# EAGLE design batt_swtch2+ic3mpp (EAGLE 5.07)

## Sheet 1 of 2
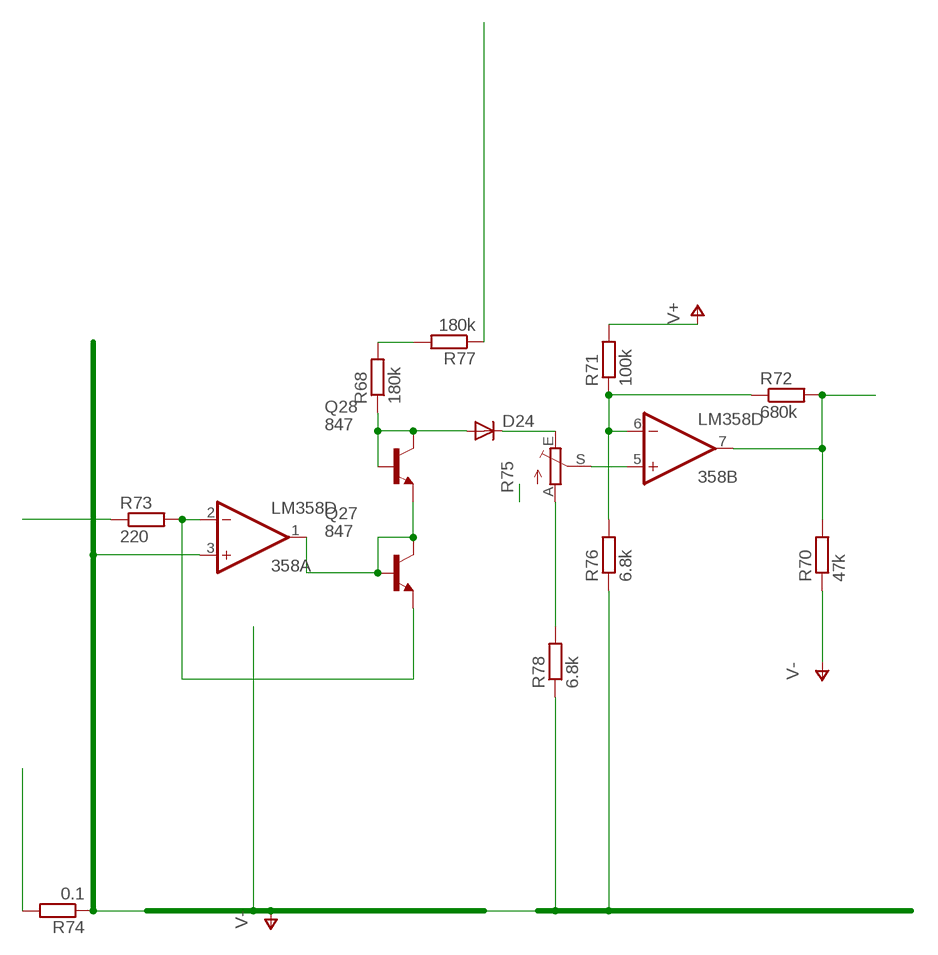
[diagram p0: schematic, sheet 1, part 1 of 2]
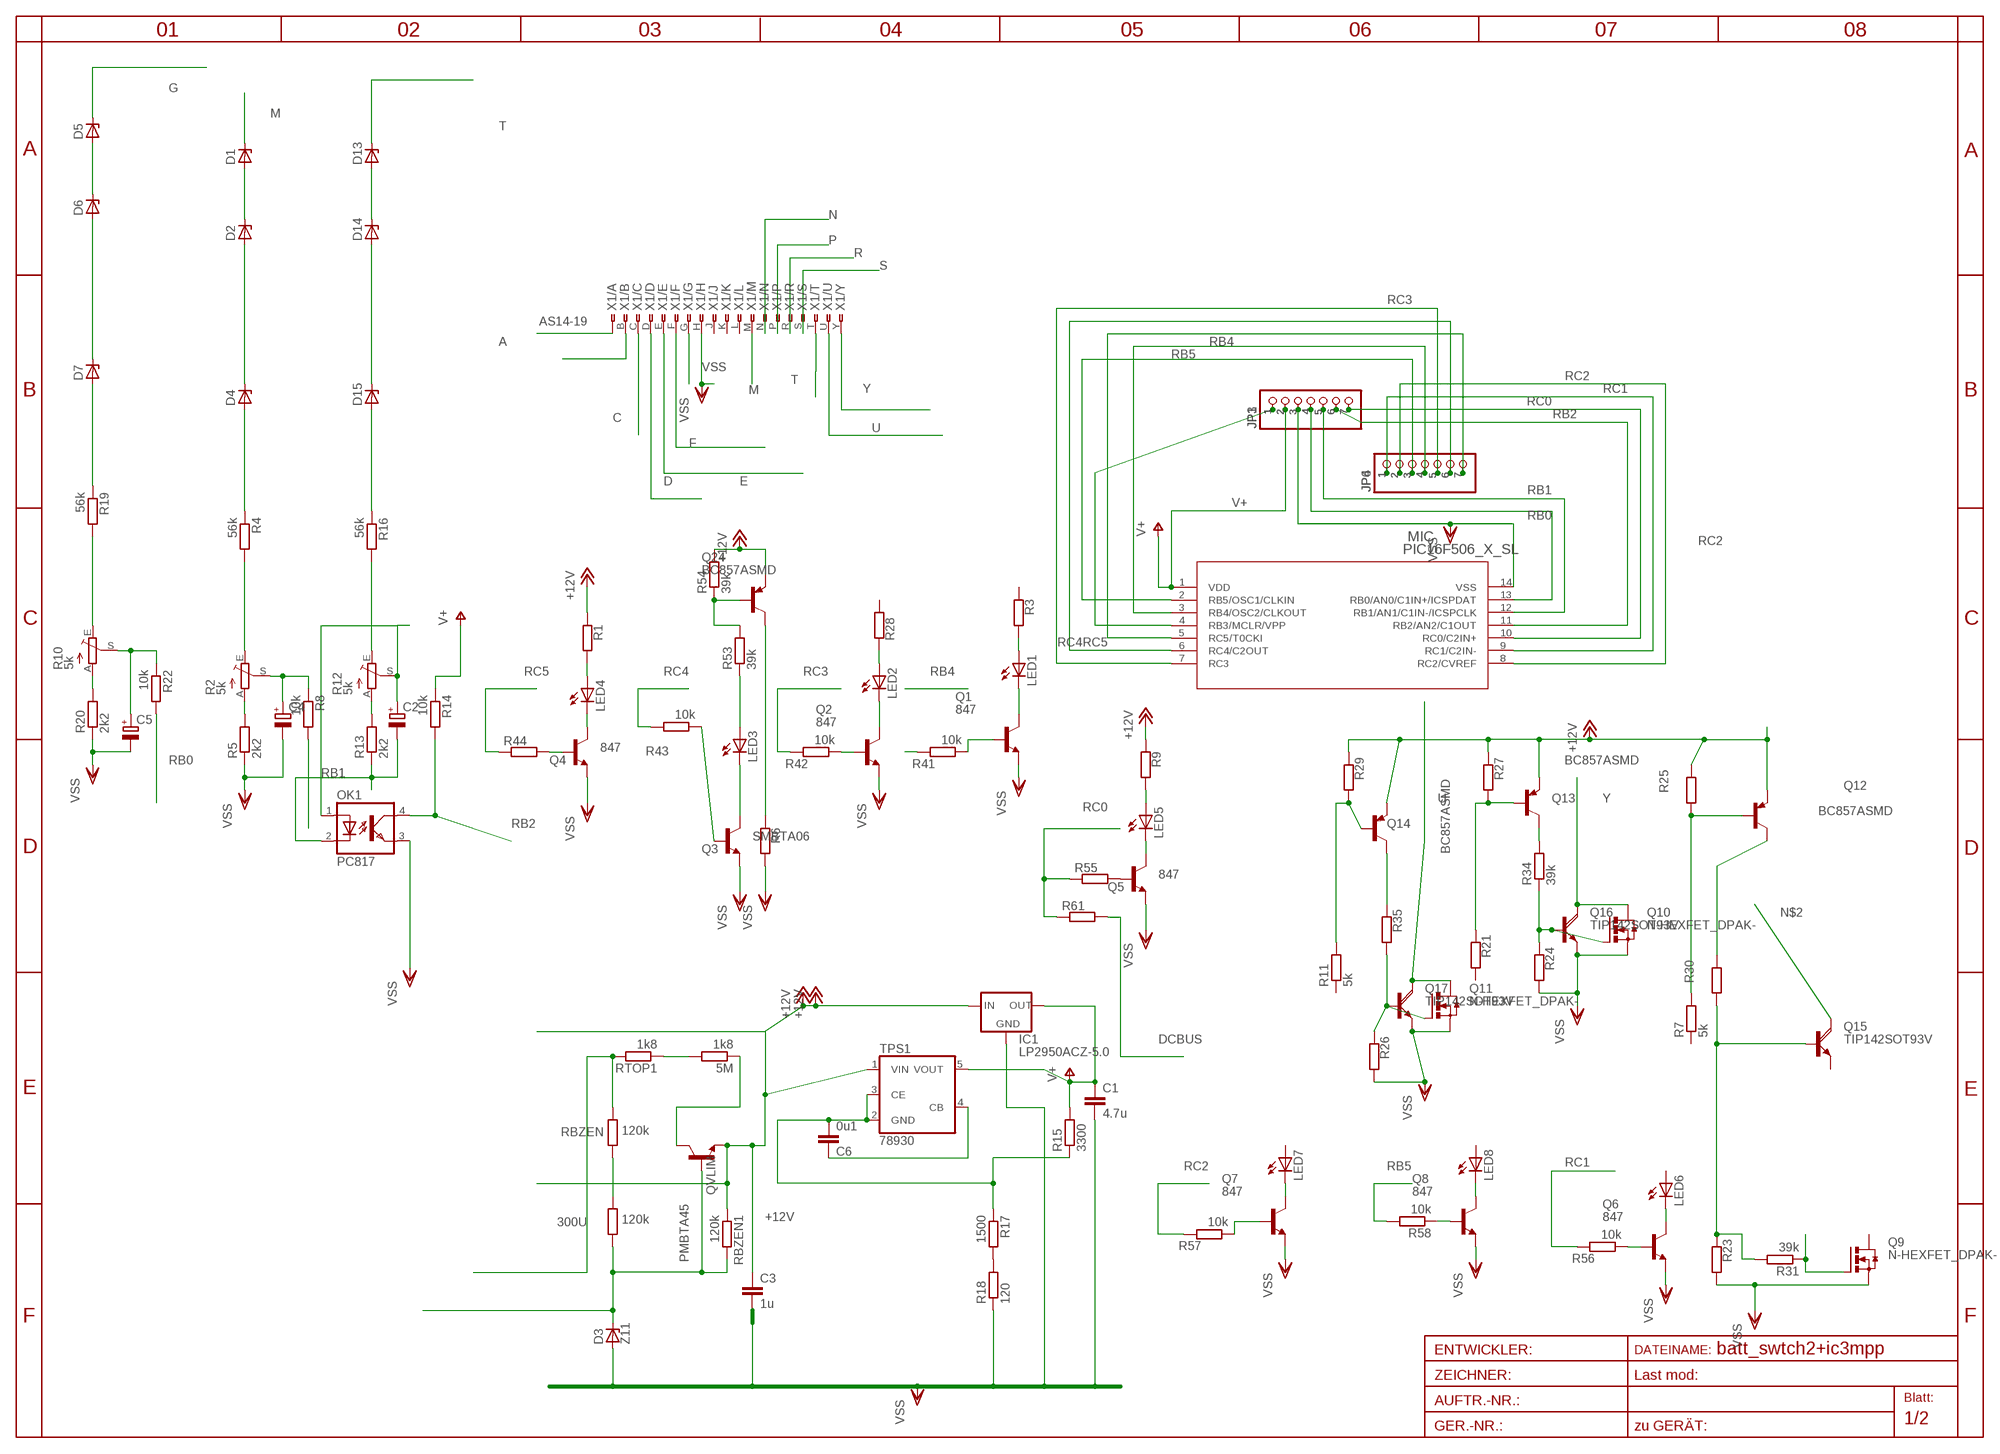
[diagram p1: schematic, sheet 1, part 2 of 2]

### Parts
5M  1k8  R-EU_R1206  [R1206]
300U  120k  R-EU_R1206  [R1206]
358  LM358D  [SO08]
C1  4.7u  C-EUC1206  [C1206]
C2  CPOL-EUE2,5-6E  [E2,5-6E]
C3  1u  C-EUC1206  [C1206]
C4  CPOL-EUE2,5-6E  [E2,5-6E]
C5  CPOL-EUE2,5-6E  [E2,5-6E]
C6  0u1  C-EUC0805  [C0805]
D1  ZENER-DIODESOD80C  [SOD80C]
D2  ZENER-DIODESOD80C  [SOD80C]
D3  Z11  ZENER-DIODESOD80C  [SOD80C]
D4  ZENER-DIODESOD80C  [SOD80C]
D5  ZENER-DIODESOD80C  [SOD80C]
D6  ZENER-DIODESOD80C  [SOD80C]
D7  ZENER-DIODESOD80C  [SOD80C]
D13  ZENER-DIODESOD80C  [SOD80C]
D14  ZENER-DIODESOD80C  [SOD80C]
D15  ZENER-DIODESOD80C  [SOD80C]
D24  DIODE-SOD80C  [SOD80C]
IC1  LP2950ACZ-5.0  [TO92]
JP1  PINHD-1X7  [1X07]
JP3  PINHD-1X7  [1X07]
JP4  PINHD-1X7  [1X07]
JP6  PINHD-1X7  [1X07]
LED1  LEDCHIPLED_1206  [CHIPLED_1206]
LED2  LEDCHIPLED_1206  [CHIPLED_1206]
LED3  LEDCHIPLED_1206  [CHIPLED_1206]
LED4  LEDCHIPLED_1206  [CHIPLED_1206]
LED5  LEDCHIPLED_1206  [CHIPLED_1206]
LED6  LEDCHIPLED_1206  [CHIPLED_1206]
LED7  LEDCHIPLED_1206  [CHIPLED_1206]
LED8  LEDCHIPLED_1206  [CHIPLED_1206]
MIC  PIC16F506_X_SL  [SOIC14_N_MC]
OK1  PC817  [DIL04]
Q1  847  BC847ASMD  [SOT23]
Q2  847  BC847ASMD  [SOT23]
Q3  SMBTA06  BC847ASMD  [SOT23]
Q4  847  BC847ASMD  [SOT23]
Q5  847  BC847ASMD  [SOT23]
Q6  847  BC847ASMD  [SOT23]
Q7  847  BC847ASMD  [SOT23]
Q8  847  BC847ASMD  [SOT23]
Q9  N-HEXFET_DPAK-  [TO252]
Q10  N-HEXFET_DPAK-  [TO252]
Q11  N-HEXFET_DPAK-  [TO252]
Q12  BC857ASMD  [SOT23-BEC]
Q13  BC857ASMD  [SOT23-BEC]
Q14  BC857ASMD  [SOT23-BEC]
Q15  TIP142SOT93V  [SOT93V]
Q16  TIP142SOT93V  [SOT93V]
Q17  TIP142SOT93V  [SOT93V]
Q24  BC857ASMD  [SOT23-BEC]
Q27  847  BC847ALT1SMD  [SOT23]
Q28  847  BC847ALT1SMD  [SOT23]
QVLIM  PMBTA45  BC847ALT1SMD  [SOT23]
R1  39k  R-EU_R0805  [R0805]
R2  5k  TRIM_EU-S64W  [S64W]
R3  39k  R-EU_R0805  [R0805]
R4  56k  R-EU_R0805  [R0805]
R5  2k2  R-EU_R0805  [R0805]
R6  39k  R-EU_R0805  [R0805]
R7  5k  R-EU_R0805  [R0805]
R8  10k  R-EU_R0805  [R0805]
R9  5k  R-EU_R0805  [R0805]
R10  5k  TRIM_EU-S64W  [S64W]
R11  5k  R-EU_R0805  [R0805]
R12  5k  TRIM_EU-S64W  [S64W]
R13  2k2  R-EU_R0805  [R0805]
R14  10k  R-EU_R0805  [R0805]
R15  3300  R-EU_R0805  [R0805]
R16  56k  R-EU_R0805  [R0805]
R17  1500  R-EU_R0805  [R0805]
R18  120  R-EU_R0805  [R0805]
R19  56k  R-EU_R0805  [R0805]
R20  2k2  R-EU_R0805  [R0805]
R21  5k  R-EU_R0805  [R0805]
R22  10k  R-EU_R0805  [R0805]
R23  39k  R-EU_R0805  [R0805]
R24  39k  R-EU_R0805  [R0805]
R25  39k  R-EU_R0805  [R0805]
R26  39k  R-EU_R0805  [R0805]
R27  39k  R-EU_R0805  [R0805]
R28  39k  R-EU_R0805  [R0805]
R29  39k  R-EU_R0805  [R0805]
R30  39k  R-EU_R0805  [R0805]
R31  39k  R-EU_R0805  [R0805]
R34  39k  R-EU_R0805  [R0805]
R35  39k  R-EU_R0805  [R0805]
R41  10k  R-EU_R0805  [R0805]
R42  10k  R-EU_R0805  [R0805]
R43  10k  R-EU_R0805  [R0805]
R44  10k  R-EU_R0805  [R0805]
R53  39k  R-EU_R0805  [R0805]
R54  39k  R-EU_R0805  [R0805]
R55  10k  R-EU_R0805  [R0805]
R56  10k  R-EU_R0805  [R0805]
R57  10k  R-EU_R0805  [R0805]
R58  10k  R-EU_R0805  [R0805]
R61  10k  R-EU_R0805  [R0805]
R68  180k  R-EU_R1206  [R1206]
R70  47k  R-EU_R0805  [R0805]
R71  100k  R-EU_R0805  [R0805]
R72  680k  R-EU_R1206  [R1206]
R73  220  R-EU_R0805  [R0805]
R74  0.1  R-EU_R2512  [R2512]
R75  TRIM_EU-S64W  [S64W]
R76  6.8k  R-EU_R0805  [R0805]
R77  180k  R-EU_R1206  [R1206]
R78  6.8k  R-EU_R0805  [R0805]
RBZEN  120k  R-EU_R1206  [R1206]
RBZEN1  120k  R-EU_R0805  [R0805]
RTOP1  1k8  R-EU_R1206  [R1206]
TPS1  78930  TPS78930SOT23-5  [SOT25]
X1  AS14-19  AS14-19OLIVE  [Y28M-19TK]

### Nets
+12V: C3.1 IC1.3(IN) Q12.E Q13.E Q14.E Q24.E QVLIM.2(E) R1.2 R9.2 R25.2 R27.2 R29.2 R54.2 RBZEN1.1 TPS1.1(VIN) ; also sheet 2
A: X1.A ; also sheet 2
BOOST_EN: Q24.C R6.2 ; also sheet 2
C: X1.C
CB: 300U.2 D3.C QVLIM.1(B) RBZEN1.2 ; also sheet 2
D: X1.D
DCBUS: R61.1 ; also sheet 2
E: X1.E
F: X1.F
G: D5.C RBZEN.1 RTOP1.2 X1.G ; also sheet 2
GND1: C6.1 TPS1.4(CB)
M: D1.C X1.M
N: X1.N
N$1: 300U.1 RBZEN.2
N$2: Q15.C
N$4: Q8.1(B) R58.1
N$5: C2.+ OK1.1(A) R12.S
N$6: Q3.1(B) R43.1
N$7: LED6.C Q6.3(C)
N$8: R17.2 R18.2
N$9: R41.2
N$10: LED8.C Q8.3(C)
N$11: Q2.1(B) R42.1
N$12: Q1.1(B) R41.1
N$14: Q5.1(B) R55.1
N$16: 5M.1 QVLIM.3(C)
N$17: LED7.C Q7.3(C)
N$18: D15.A R16.1
N$19: LED1.C Q1.3(C)
N$20: LED1.A R3.1
N$21: Q14.B R11.2 R29.1
N$22: LED2.C Q2.3(C)
N$23: D14.A D15.C
N$24: D13.A D14.C
N$25: LED2.A R28.1
N$26: R12.A R13.2
N$28: Q6.1(B) R56.1
N$29: 5M.2 RTOP1.1
N$30: Q4.1(B) R44.1
N$31: Q7.1(B) R57.1
N$32: LED3.C Q3.3(C)
N$33: LED4.C Q4.3(C)
N$34: D7.A R19.1
N$35: D6.A D7.C
N$36: LED4.A R1.1
N$37: Q12.C R30.2
N$38: D5.A D6.C
N$39: R10.E R19.2
N$40: R10.A R20.2
N$41: D4.A R4.1
N$42: D2.A D4.C
N$43: D1.A D2.C
N$44: R2.E R4.2
N$45: R2.A R5.2
N$46: C4.+ R2.S R8.1
N$47: LED5.A R9.1
N$48: C5.+ R10.S R22.1
N$49: Q14.C R35.2
N$50: Q15.B R23.2 R30.1 R31.2
N$51: Q10.1(G) Q16.B R24.2 R34.1
N$52: LED5.C Q5.3(C)
N$53: Q12.B R7.2 R25.1
N$54: Q9.1(G) R31.1
N$55: Q13.B R21.2 R27.1
N$57: Q13.C R34.2
N$59: Q11.1(G) Q17.B R26.2 R35.1
N$65: R12.E R16.2
N$75: 358.2(A:-IN) Q27.2(E) R73.2
N$81: Q24.B R53.2 R54.1
N$82: LED3.A R53.1
N$85: 358.1(A:OUT) Q27.1(B) Q27.3(C) Q28.2(E)
N$88: D24.A Q28.1(B) Q28.3(C) R68.1
N$90: R73.1 R74.2
N$91: D24.C R75.E
N$92: 358.5(B:+IN) R75.S
N$93: 358.6(B:-IN) R71.1 R72.1 R76.2
N$94: R68.2 R77.2
N$95: 358.7(B:OUT) R70.2 R72.2
N$97: R75.A R78.2
P: X1.P
R: X1.R
RB0: JP1.4 JP3.4 MIC.13(RB0/AN0/C1IN+/ICSPDAT) R22.2
RB1: JP1.5 JP3.5 MIC.12(RB1/AN1/C1IN-/ICSPCLK) R8.2
RB2: JP1.6 JP3.6 MIC.11(RB2/AN2/C1OUT) OK1.4(COL) R14.2
RB4: JP4.4 JP6.4 MIC.3(RB4/OSC2/CLKOUT)
RB5: JP4.3 JP6.3 MIC.2(RB5/OSC1/CLKIN) R58.2
RC0: JP1.7 JP3.7 MIC.10(RC0/C2IN+) R55.2 R61.2
RC1: JP4.1 JP6.1 MIC.9(RC1/C2IN-) R56.2
RC2: JP4.2 JP6.2 MIC.8(RC2/CVREF) R57.2
RC3: JP4.5 JP6.5 MIC.7(RC3) R42.2
RC4: JP4.6 JP6.6 MIC.6(RC4/C2OUT) R43.2
RC5: JP4.7 JP6.7 MIC.5(RC5/T0CKI) R44.2
S: C2.- OK1.2(C) R13.1 X1.S
T: D13.C X1.T
U: Q11.3(D) Q17.C X1.U
V+: C1.1 IC1.1(OUT) JP1.2 JP3.2 MIC.1(VDD) R14.1 R15.2 R71.2 TPS1.5(VOUT)
V-: 358.3(A:+IN) C6.2 R15.1 R17.1 R70.1 R74.1 R76.1 R78.1 TPS1.2(GND) TPS1.3(CE)
VPLUS: R77.1
VSS: C1.2 C3.2 C4.- C5.- D3.A IC1.2(GND) JP1.3 JP3.3 MIC.14(VSS) OK1.3(EMIT) Q1.2(E) Q2.2(E) Q3.2(E) Q4.2(E) Q5.2(E) Q6.2(E) Q7.2(E) Q8.2(E) Q9.2(S) Q10.2(S) Q11.2(S) Q16.E Q17.E R5.1 R6.1 R18.1 R20.1 R23.1 R24.1 R26.1 X1.B X1.H ; also sheet 2
WIND: JP1.1 JP3.1 MIC.4(RB3/MCLR/VPP)
Y: Q10.3(D) Q16.C X1.Y
Unconnected: LED6.A LED7.A LED8.A Q9.3(D) Q15.E R3.2 R7.1 R11.1 R21.1 R28.2 X1.J X1.K X1.L

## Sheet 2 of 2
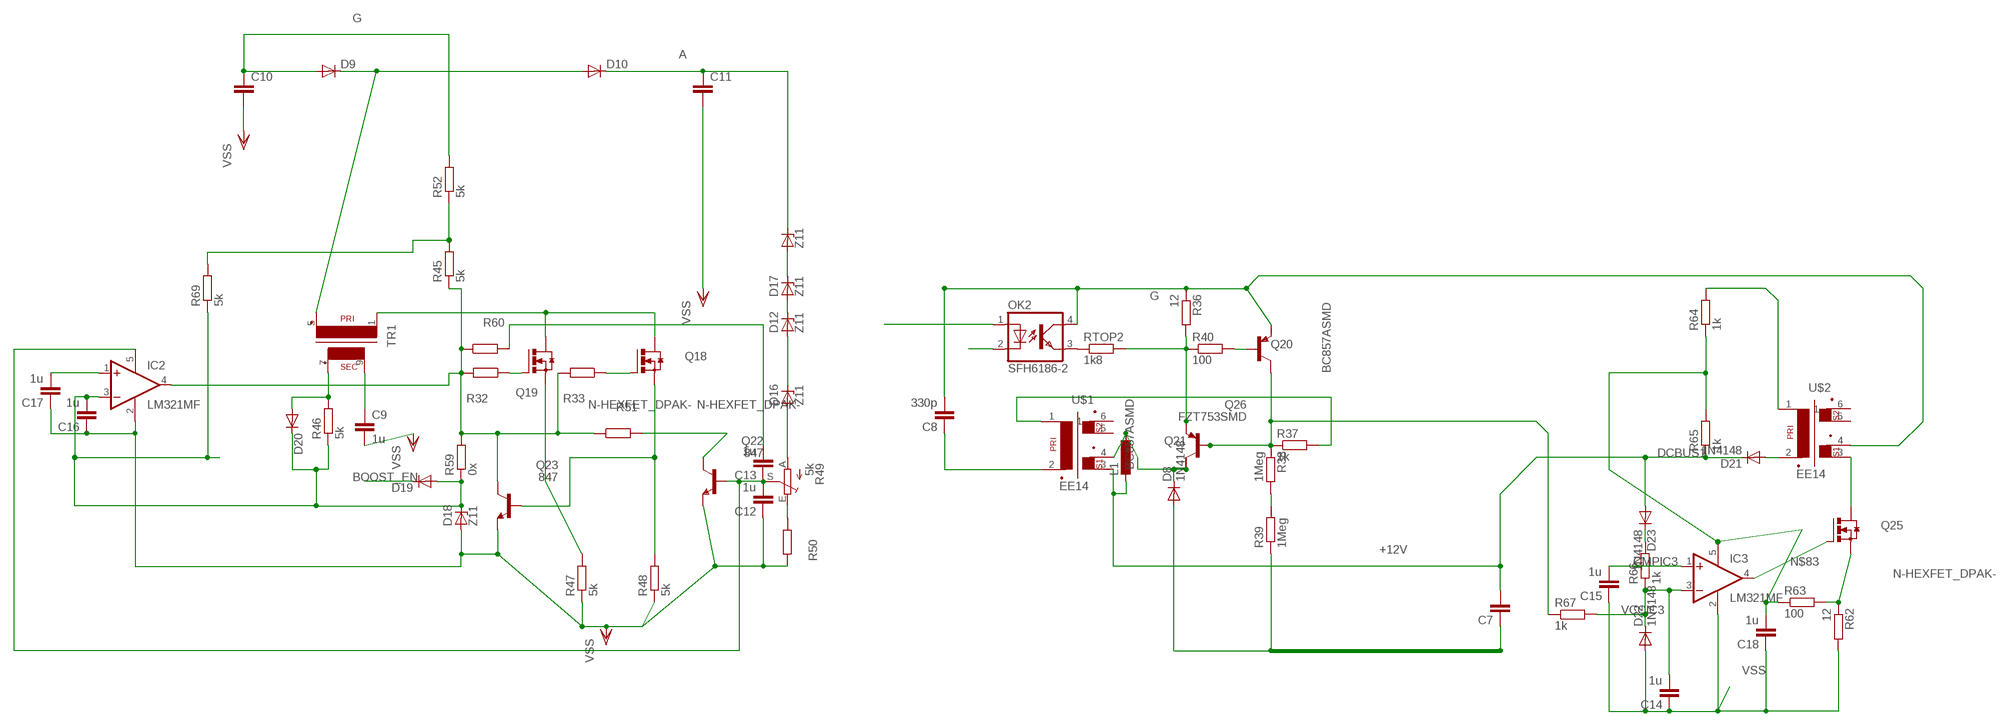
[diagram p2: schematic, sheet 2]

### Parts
C7  C-EU025-025X050  [C025-025X050]
C8  330p  C-EUC0805  [C0805]
C9  1u  C-EUC1206  [C1206]
C10  C-EU075-052X106  [C075-052X106]
C11  C-EU075-052X106  [C075-052X106]
C12  1u  C-EUC1206  [C1206]
C13  1u  C-EUC1206  [C1206]
C14  1u  C-EUC0805  [C0805]
C15  1u  C-EUC0805  [C0805]
C16  1u  C-EUC0805  [C0805]
C17  1u  C-EUC0805  [C0805]
C18  1u  C-EUC0805  [C0805]
D8  1N4148  DIODE-SMA-DO214  [SMA-DO214AC]
D9  DIODE-SMC  [SMC]
D10  DIODE-SMC  [SMC]
D11  Z11  ZENER-DIODESOD80C  [SOD80C]
D12  Z11  ZENER-DIODESOD80C  [SOD80C]
D16  Z11  ZENER-DIODESOD80C  [SOD80C]
D17  Z11  ZENER-DIODESOD80C  [SOD80C]
D18  Z11  ZENER-DIODESOD80C  [SOD80C]
D19  DIODE-MINIMELF  [MINIMELF]
D20  DIODE-MINIMELF  [MINIMELF]
D21  1N4148  DIODE-SMA-DO214  [SMA-DO214AC]
D22  1N4148  DIODE-SMA-DO214  [SMA-DO214AC]
D23  1N4148  DIODE-SMA-DO214  [SMA-DO214AC]
IC2  LM321MF  [SOT23-5]
IC3  LM321MF  [SOT23-5]
L1  L-EU0204/5  [0204/5]
OK2  SFH6186-2  [SMD4]
Q18  N-HEXFET_DPAK-  [TO252]
Q19  N-HEXFET_DPAK-  [TO252]
Q20  BC857ASMD  [SOT23-BEC]
Q21  BC857ASMD  [SOT23-BEC]
Q22  847  BC847ASMD  [SOT23]
Q23  847  BC847ASMD  [SOT23]
Q25  N-HEXFET_DPAK-  [TO252]
Q26  FZT753SMD  [SOT223]
R32  39k  R-EU_R0805  [R0805]
R33  39k  R-EU_R0805  [R0805]
R36  12  R-EU_R0805  [R0805]
R37  1k  R-EU_R0805  [R0805]
R38  1Meg  R-EU_R1206  [R1206]
R39  1Meg  R-EU_R1206  [R1206]
R40  100  R-EU_R0805  [R0805]
R45  5k  R-EU_R1206  [R1206]
R46  5k  R-EU_R0805  [R0805]
R47  5k  R-EU_R2010  [R2010]
R48  5k  R-EU_R2010  [R2010]
R49  5k  TRIM_EU-S64W  [S64W]
R50  39k  R-EU_R0805  [R0805]
R51  39k  R-EU_R0805  [R0805]
R52  5k  R-EU_R1206  [R1206]
R59  0x  R-EU_R0402  [R0402]
R60  39k  R-EU_R0805  [R0805]
R62  12  R-EU_R0805  [R0805]
R63  100  R-EU_R0805  [R0805]
R64  1k  R-EU_R0805  [R0805]
R65  1k  R-EU_R0805  [R0805]
R66  1k  R-EU_R0805  [R0805]
R67  1k  R-EU_R0805  [R0805]
R69  5k  R-EU_0207/22  [0207/22]
RTOP2  1k8  R-EU_R1206  [R1206]
TR1  VR11  [1X3WDIRVER]
U$1  EE14  [EE14]
U$2  EE14  [EE14]

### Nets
+12V: C7.2 D21.K(C) D23.A L1.2 OK2.1(A) R65.1 U$1.3 ; also sheet 1
A: C11.1 D10.C D11.C ; also sheet 1
B1C2: Q20.C Q21.B Q26.1(B) R37.1 R38.1 R67.1
BOOST_EN: D19.C ; also sheet 1
C1: D8.K(C) L1.1 Q21.C Q26.2(C) U$1.4
CB: OK2.2(C) ; also sheet 1
CMPIC3: C15.2 IC3.1(+IN)
DCBUS: C12.2 C13.1 IC2.5(V+) Q22.1(B) R49.S ; also sheet 1
DCBUS1: C18.2 IC3.5(V+) R63.1 R64.1 R65.2
EB: Q21.E Q26.3(E) R36.2 R40.1 RTOP2.2
G: C8.2 C10.1 D9.A OK2.4(COL) Q20.E R36.1 R52.2 U$2.4 ; also sheet 1
N$3: OK2.3(EMIT) RTOP2.1
N$13: D9.C D10.A TR1.5(P2)
N$15: Q18.3(D) Q19.3(D) TR1.1
N$27: C16.2 D18.C D19.A D20.C IC2.3(-IN) R46.1 R59.1 R69.1
N$56: Q18.1(G) R33.1
N$58: Q19.1(G) R32.1
N$60: R37.2 U$1.1
N$61: C8.1 U$1.2
N$62: R38.2 R39.2
N$63: Q20.B R40.2
N$64: D20.A R46.2 TR1.7(S3)
N$66: IC2.4(OUT) Q23.3(C) R32.2 R33.2 R45.1 R51.1 R59.2 R60.1
N$67: C13.2 R60.2
N$68: Q19.2(S) R47.2
N$69: Q25.3(D) U$2.3
N$71: Q22.3(C) R51.2
N$72: Q18.2(S) Q23.1(B) R48.2
N$73: D16.A R49.A
N$74: C9.1 TR1.9(S4)
N$76: D12.A D16.C
N$77: D12.C D17.A
N$78: R49.E R50.1
N$79: D11.A D17.C
N$80: R45.2 R52.1 R69.2
N$83: IC3.4(OUT) Q25.1(G)
N$84: D23.K(C) R66.2
N$86: Q25.2(S) R62.1 R63.2
N$87: D21.A U$2.2
N$96: C17.2 IC2.1(+IN)
VCCIC3: C14.2 D22.K(C) IC3.3(-IN) R66.1 R67.2
VSS: C7.1 C9.2 C10.2 C11.2 C12.1 C14.1 C15.1 C16.1 C17.1 C18.1 D8.A D18.A D22.A IC2.2(V-) IC3.2(V-) Q22.2(E) Q23.2(E) R39.1 R47.1 R48.1 R50.2 R62.2 R64.2 U$2.1 ; also sheet 1
Unconnected: Q26.4(C/) U$1.5 U$1.6 U$2.5 U$2.6

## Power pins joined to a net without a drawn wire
V+: 358.8(P:V+)
V-: 358.4(P:V-)

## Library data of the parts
5M 300U R4 R5 R8 R13-R20 R22 R36-R40 R62-R68 R70-R74 R76-R78 RBZEN RBZEN1 RTOP1 RTOP2 = rcl:R-EU_: RESISTOR, European symbol
358 = linear:LM358: OP AMP also LM158; LM258; LM2904 Source: http://cache.national.com/ds/LM/LM158.pdf
C1 C3 C6-C18 = rcl:C-EU: CAPACITOR, European symbol
C2 C4 C5 = rcl:CPOL-EU: POLARIZED CAPACITOR, European symbol
D1-D7 D11-D18 = diode:ZENER-DIODE: Z-Diode
D8-D10 D19-D24 = diode:DIODE-: DIODE
IC1 = v-reg:LP2950?*: Source: http://cache.national.com/ds/LP/LP2950.pdf
IC2 IC3 = linear:LM321?*: Low Power Single Op Amp Source: http://cache.national.com/ds/LM/LM321.pdf
JP1 JP3 JP4 JP6 = pinhead:PINHD-1X7: PIN HEADER
L1 = rcl:L-EU: INDUCTOR, European symbol
LED1-LED8 = led:LED: LED
MIC = pic16f506mc:PIC16F506_X_SL
OK1 = optocoupler:PC817: SHARP OPTO COUPLER
OK2 = optocoupler:SFH618?*: Optocoupler, Phototransistor Output, Low Input Current Source: http://www.vishay.com/docs/83673/sfh618.pdf
Q1-Q8 Q22 Q23 Q27 Q28 QVLIM = transistor-npn:BC847*: NPN Transistor
Q9-Q11 Q18 Q19 Q25 = transistor-power:N-HEXFET_?-*: HEXFET® Power MOSFET
Q12-Q14 Q20 Q21 Q24 = transistor-pnp:BC857*: PNP Transistror
Q15-Q17 = transistor-power:TIP142: NPN DARLINGTON TRANSISTOR
Q26 = transistor-pnp:FZT753SMD: PNP Transistor
R1 R3 R6 R7 R9 R11 R21 R23-R35 R41-R48 R50-R61 R69 = rcl-2:R-EU_: RESISTOR, European symbol
R2 R10 R12 R49 R75 = pot:TRIM_EU-: POTENTIOMETER
TPS1 = v-reg:TPS78930
TR1 = trafo:VR11: TRANSFORMER 1 primary winding, 1 secondary winding BLOCK
U$1 U$2 = trafo:EE14
X1 = con-deutsch:AS14-19: DEUTSCH Connector

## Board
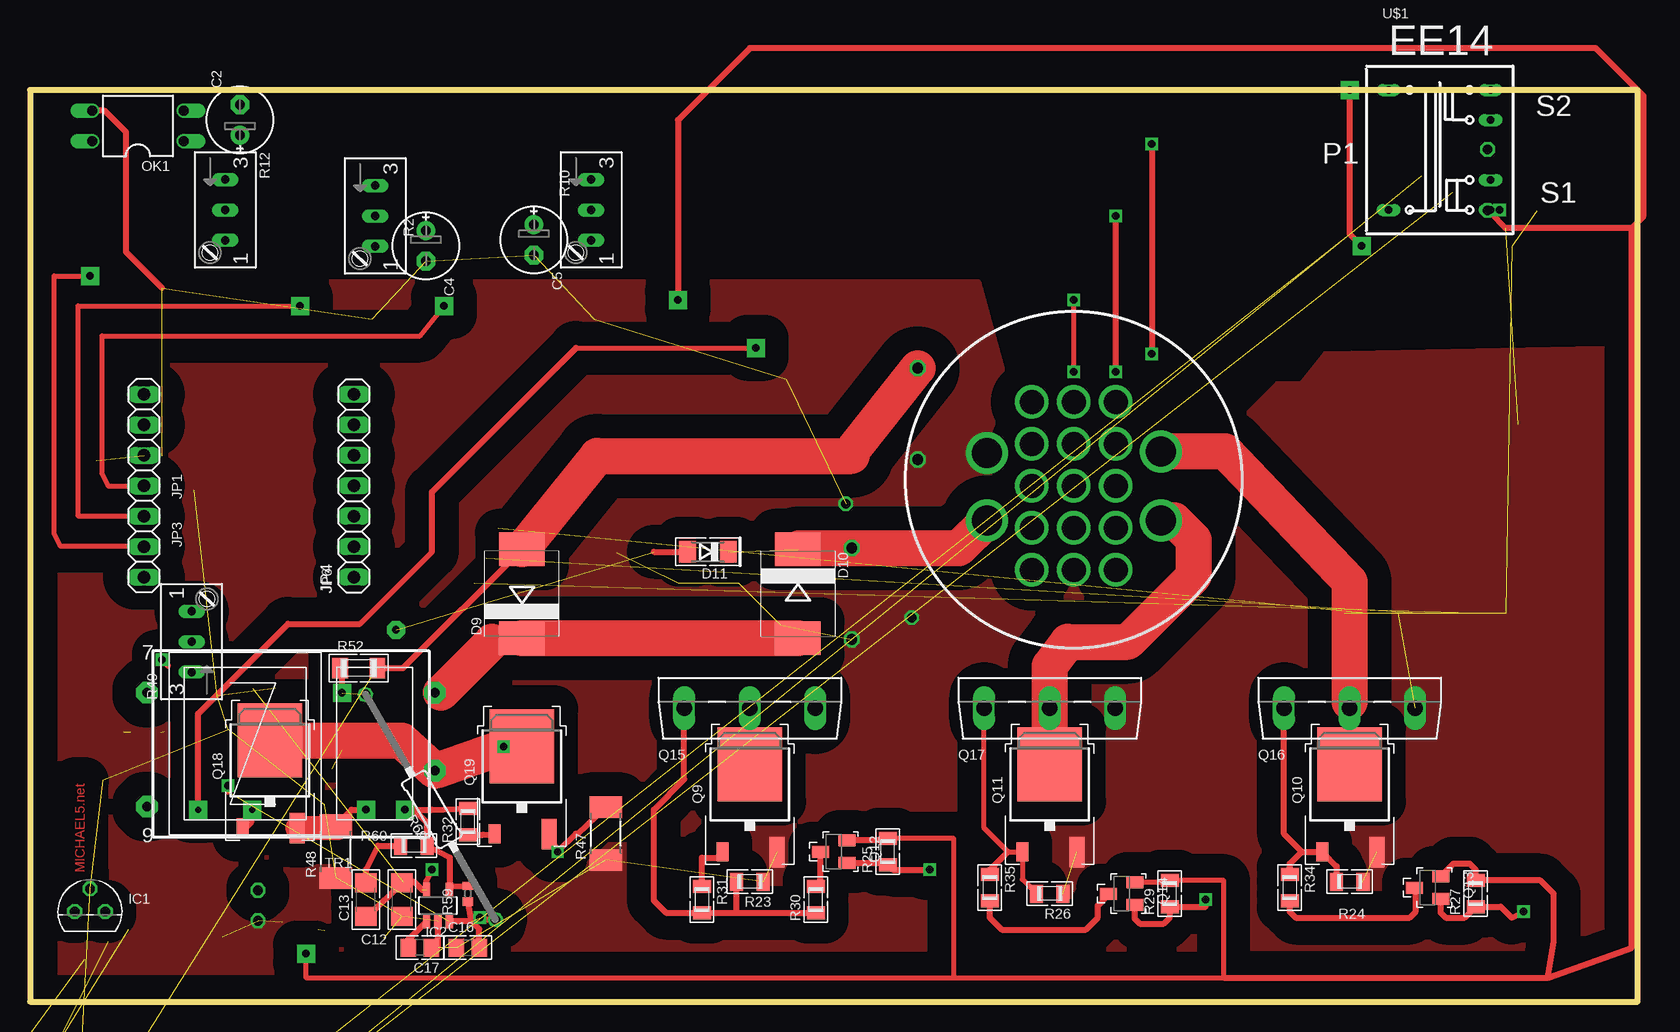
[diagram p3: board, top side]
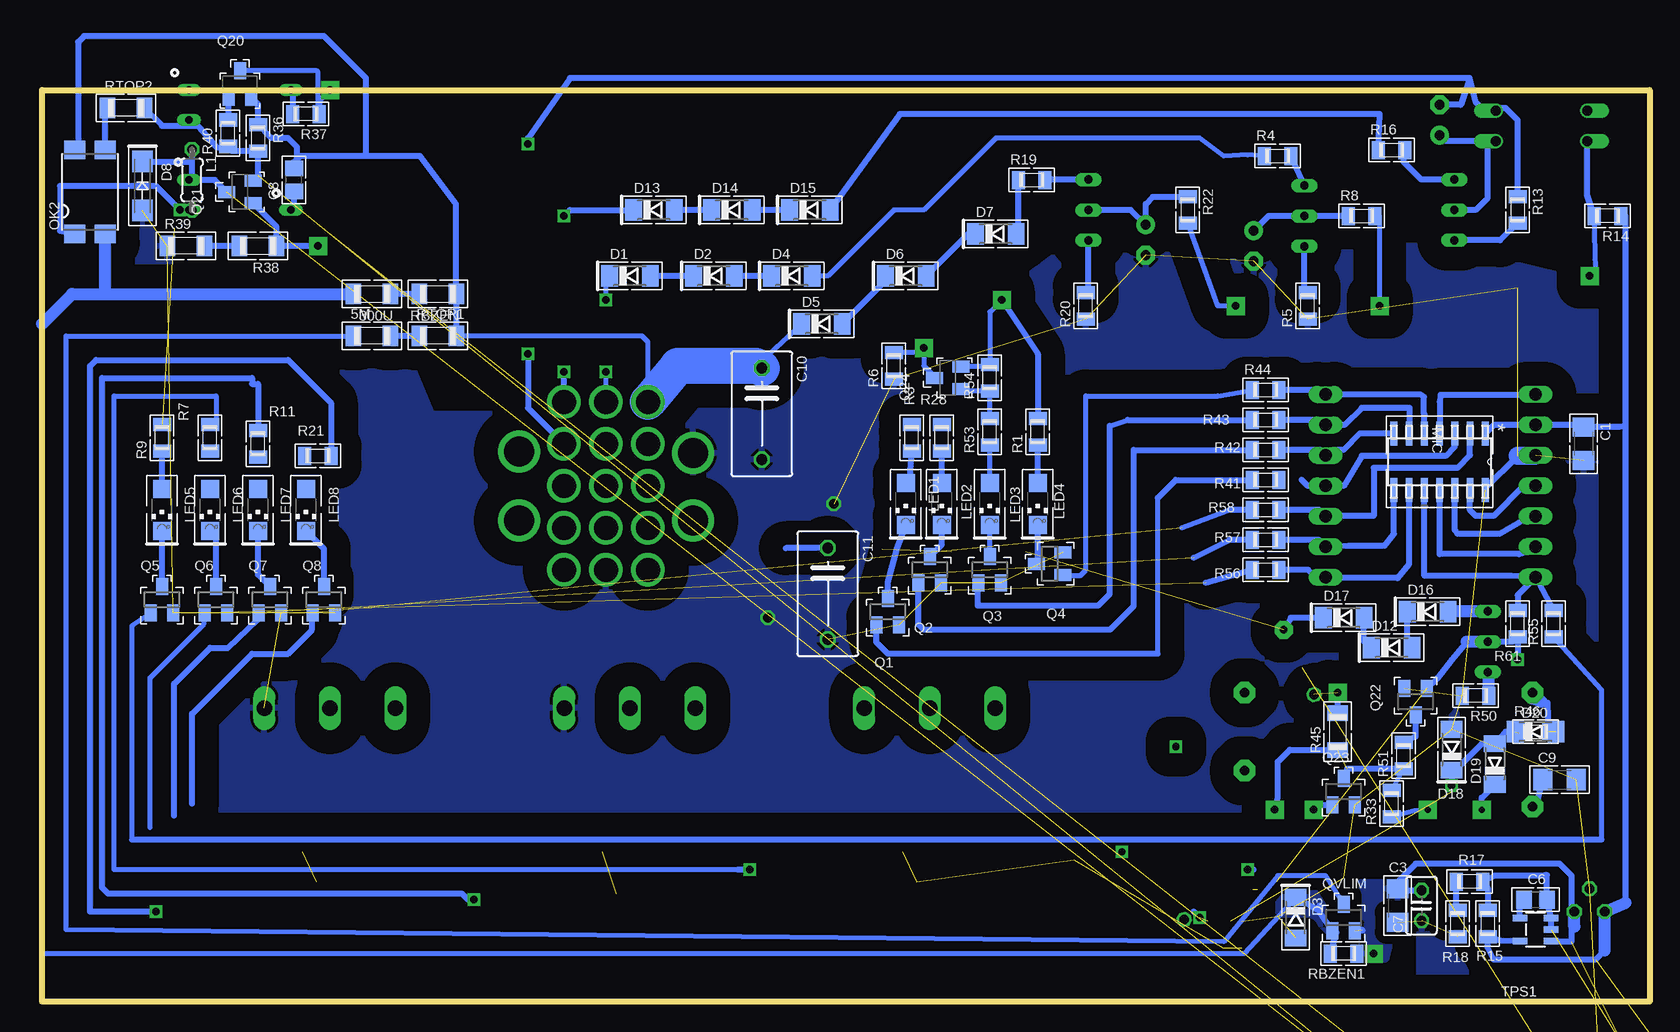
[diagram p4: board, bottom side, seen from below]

Size 134 x 76 mm. Coordinates in mm from the lower left corner, seen from the top.
Outline: 134,0 134,76 0,76 0,0 134,0
Copper layers (1*16): Top 0.035mm / dielectric 1.5mm / Bottom 0.035mm
Design rules "default *": minimum track width 40mil, minimum drill 30mil, track to track 8mil, track to pad 8mil, pad to pad 8mil, via to via 8mil, smd to smd 8mil, copper to edge 40mil, drill to drill 8mil, minimum pad ring 8mil, minimum via ring 8mil, stop-mask expansion 4mil, vias tented up to drill 0mil, thermal gap 10mil

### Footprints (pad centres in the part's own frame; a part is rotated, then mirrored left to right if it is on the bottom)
R1206 = smd 1.3 x 1.7: 1 -1.55,0; 2 1.55,0
SO08 = smd 0.6 x 2.2: 1 -1.905,-2.6; 2 -0.635,-2.6; 3 0.635,-2.6; 4 1.905,-2.6; 5 1.905,2.6; 6 0.635,2.6; 7 -0.635,2.6; 8 -1.905,2.6
C1206 = smd 1.6 x 1.8: 1 -1.4,0; 2 1.4,0
E2,5-6E = drill 0.813 pad 1.575 round: + -1.27,0 | drill 0.813 pad 1.575 octagon: - 1.27,0
C0805 = smd 1.3 x 1.5: 1 -0.95,0; 2 0.95,0
C025-025X050 = drill 0.813 octagon: 1 -1.27,0; 2 1.27,0
C075-052X106 = drill 0.914 octagon: 1 -3.81,0; 2 3.81,0
SOD80C = smd 1.4 x 1.8: A 1.7,0; C -1.7,0
SMA-DO214AC = smd 1.8 x 1.7: A 2.05,-0.127; K -2.05,-0.127
SMC = smd 2.8 x 3.8: A 3.7,0; C -3.7,0
MINIMELF = smd 1.4 x 1.8: A 1.7,0; C -1.7,0
TO92 = drill 0.813 octagon: 1 -1.27,0; 2 0,1.905; 3 1.27,0
SOT23-5 = smd 0.6 x 1.2: 1 -0.95,-1.306; 2 0,-1.306; 3 0.95,-1.306; 4 0.95,1.306; 5 -0.95,1.306
1X07 = drill 1.016 long: 1 -7.62,0; 2 -5.08,0; 3 -2.54,0; 4 0,0; 5 2.54,0; 6 5.08,0; 7 7.62,0
0204/5 = drill 0.813 octagon: 1 -2.54,0; 2 2.54,0
CHIPLED_1206 = smd 1.5 x 1.5: A 0,-1.75; C 0,1.75
SOIC14_N_MC = smd 1.981 x 0.559: 1 -2.362,3.81; 2 -2.362,2.54; 3 -2.362,1.27; 4 -2.362,0; 5 -2.362,-1.27; 6 -2.362,-2.54; 7 -2.362,-3.81; 8 2.362,-3.81; 9 2.362,-2.54; 10 2.362,-1.27; 11 2.362,0; 12 2.362,1.27; 13 2.362,2.54; 14 2.362,3.81
DIL04 = drill 0.813 offset: 1 -1.27,-3.81; 2 1.27,-3.81; 3 1.27,3.81; 4 -1.27,3.81
SMD4 = smd 1.78 x 1.55: 1 -1.27,-3.5; 2 1.27,-3.5; 3 1.27,3.5; 4 -1.27,3.5
SOT23 = smd 1 x 1.4: 1 -0.95,-1.1; 2 0.95,-1.1; 3 0,1.1
TO252 = smd 1 x 1.6: 1 -2.28,-3.53 | smd 1.27 x 2.54: 2 2.28,-3.53 | smd 5.4 x 6.2: 3 0,3.77
SOT23-BEC = smd 1 x 1.4: B -0.95,-1.1; C 0,1.1; E 0.95,-1.1
SOT93V = drill 1.3 pad 1.676 long: B -5.461,-2.54; C 0,-2.54; E 5.461,-2.54
SOT223 = smd 1.219 x 2.235: 1 -2.311,-3.099; 2 0,-3.099; 3 2.311,-3.099 | smd 3.6 x 2.2: 4 0,3.099
R0805 = smd 1.1 x 1.5: 1 -1.1,0; 2 1.1,0
S64W = drill 0.7 long: A 2.54,1.27; E -2.54,1.27; S 0,1.27
R2010 = smd 1.8 x 2.7: 1 -2.2,0; 2 2.2,0
R0402 = smd 0.7 x 0.9: 1 -0.65,0; 2 0.65,0
0207/22 = drill 0.813 octagon: 1 -10.58,0; 2 11.08,0
R2512 = smd 1.8 x 3.4: 1 -3.1,0; 2 3.1,0
SOT25 = smd 0.55 x 1.2: 1 -0.95,-1.3; 2 0,-1.3; 3 0.95,-1.3; 4 0.95,1.3; 5 -0.95,1.3
1X3WDIRVER = drill 0.8 pad 1.778 octagon: 1 -12,2.25; 5 -12,-4.25; 7 12,-4.25; 9 12,5.25
EE14 = drill 0.6 pad 1 long: 1 4.25,-5; 2 4.25,5; 3 -4.25,5 | drill 0.6 pad 1.016 long: 4 -4.25,2.5; 5 -4.25,-2.5; 6 -4.25,-5
Y28M-19TK = drill 2.5 pad 3.5 round: A -7.25,-2.875; B -7.25,2.75; U 7.25,-2.875; Y 7.25,2.875 | drill 2 pad 2.54 round: C -3.5,-7; D -3.5,-3.5; E -3.5,0; F -3.5,3.5; G -3.5,7; H 0,-7; J 0,-3.5; K 0,0; L 0,3.5; M 0,7; N 3.5,-7; P 3.5,-3.5; R 3.5,0; S 3.5,3.5; T 3.5,7

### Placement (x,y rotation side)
5M  106.5,55.5 0 bottom
300U  106.5,59 180 bottom
358  not placed on the board
C1  5.5,46.5 270 bottom
C2  17.5,73.5 90 top
C3  21,8 270 bottom
C4  33,63 270 top
C5  42,63.5 270 top
C6  9.5,8.5 0 bottom
C7  19,8 90 bottom
C8  113,68.5 90 bottom
C9  7.5,18.5 0 bottom
C10  74,49 270 bottom
C11  68.5,34 270 bottom
C12  31,8.5 90 top
C13  28,8.5 90 top
C14  not placed on the board
C15  not placed on the board
C16  36.5,4.5 0 top
C17  32.5,4.5 180 top
C18  not placed on the board
D1  85,60.5 0 bottom
D2  78,60.5 0 bottom
D3  29.5,7 270 bottom
D4  71.5,60.5 0 bottom
D5  69,56.5 0 bottom
D6  62,60.5 0 bottom
D7  54.5,64 0 bottom
D8  125.5,68 270 bottom
D9  41,34 90 top
D10  64,34 270 top
D11  56.5,37.5 180 top
D12  21.5,29.5 0 bottom
D13  83,66 0 bottom
D14  76.5,66 0 bottom
D15  70,66 0 bottom
D16  18.5,32.5 0 bottom
D17  25.5,32 0 bottom
D18  16.5,21 90 bottom
D19  12.9,19.8 90 bottom
D20  9.5,22.5 0 bottom
D21  not placed on the board
D22  not placed on the board
D23  not placed on the board
D24  not placed on the board
IC1  5,7.5 0 top
IC2  34,8 0 top
IC3  not placed on the board
JP1  9.5,43 270 top
JP3  9.5,43 270 top
JP4  27,43 90 top
JP6  27,43 90 top
L1  121.5,68.5 270 bottom
LED1  62,41.5 180 bottom
LED2  59,41.5 180 bottom
LED3  55,41.5 180 bottom
LED4  51,41.5 180 bottom
LED5  124,41 180 bottom
LED6  120,41 180 bottom
LED7  116,41 180 bottom
LED8  112,41 180 bottom
MIC  17.5,45 270 bottom
OK1  9,73 90 top
OK2  130,67.5 0 bottom
Q1  63.5,32.5 0 bottom
Q2  60,36 0 bottom
Q3  55,36 0 bottom
Q4  50,36.5 90 bottom
Q5  124,33.5 0 bottom
Q6  119.5,33.5 0 bottom
Q7  115,33.5 0 bottom
Q8  110.5,33.5 0 bottom
Q9  60,16 0 top
Q10  110,16 0 top
Q11  85,16 0 top
Q12  67,12.5 90 top
Q13  116.5,9.5 90 top
Q14  91,9 90 top
Q15  60,27 0 top
Q16  110,27 0 top
Q17  85,27 0 top
Q18  20,18 0 top
Q19  41,17.5 0 top
Q20  117.5,76.5 0 bottom
Q21  117.5,67.5 90 bottom
Q22  19.5,25 180 bottom
Q23  25.5,17.5 0 bottom
Q24  58.5,52 90 bottom
Q25  not placed on the board
Q26  not placed on the board
Q27  not placed on the board
Q28  not placed on the board
QVLIM  25.5,7 0 bottom
R1  51,47.5 90 bottom
R2  27.5,65.5 270 top
R3  61.5,47 90 bottom
R4  31,70.5 0 bottom
R5  28.5,58 90 bottom
R6  63,53 90 bottom
R7  120,47 90 bottom
R8  24,65.5 0 bottom
R9  124,47 90 bottom
R10  45.5,66 270 top
R11  116,46.5 90 bottom
R12  15,66 270 top
R13  11,66 270 bottom
R14  3.5,65.5 180 bottom
R15  13.5,6.5 270 bottom
R16  21.5,71 0 bottom
R17  15,10 180 bottom
R18  16,6.5 90 bottom
R19  51.5,68.5 0 bottom
R20  47,58 90 bottom
R21  111,45.5 0 bottom
R22  38.5,66 270 bottom
R23  60,10 180 top
R24  110,10 180 top
R25  71.5,12.5 90 top
R26  85,9 180 top
R27  120.5,9 90 top
R28  59,47 90 bottom
R29  95,9 90 top
R30  65.5,8.5 90 top
R31  56,8.5 270 top
R32  36.5,15 90 top
R33  21.5,16.5 90 bottom
R34  105,9.5 270 top
R35  80,9.5 270 top
R36  116,72 270 bottom
R37  112,74 180 bottom
R38  116,63 180 bottom
R39  122,63 0 bottom
R40  118.5,72.4 90 bottom
R41  32,43.5 0 bottom
R42  32,46 0 bottom
R43  32,48.5 0 bottom
R44  32,51 0 bottom
R45  26,22.5 90 bottom
R46  9.5,22.5 0 bottom
R47  48,14 90 top
R48  25.5,12.5 90 top
R49  14.75,30 90 top
R50  14.5,25.5 180 bottom
R51  20.5,20.5 90 bottom
R52  27.4,27.8 0 top
R53  55,47.5 90 bottom
R54  55,52 90 bottom
R55  8,31.5 90 bottom
R56  32,36 0 bottom
R57  32,38.5 0 bottom
R58  32,41 0 bottom
R59  36.5,9 90 top
R60  32,13 180 top
R61  11,31.5 90 bottom
R62  not placed on the board
R63  not placed on the board
R64  not placed on the board
R65  not placed on the board
R66  not placed on the board
R67  not placed on the board
R68  not placed on the board
R69  33.5,16 120 top
R70  not placed on the board
R71  not placed on the board
R72  not placed on the board
R73  not placed on the board
R74  not placed on the board
R75  not placed on the board
R76  not placed on the board
R77  not placed on the board
R78  not placed on the board
RBZEN  101,59 180 bottom
RBZEN1  25.5,4 180 bottom
RTOP1  101,55.5 0 bottom
RTOP2  127,74.5 0 bottom
TPS1  9.5,6 90 bottom
TR1  21.75,21.5 180 top
U$1  117.5,71 180 top
U$2  not placed on the board
X1  87,43 0 top

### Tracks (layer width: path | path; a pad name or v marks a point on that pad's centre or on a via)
+12V  (via drill 0.6, 0.6 pad 1.5)  (5 unrouted)
  Top 0.406: Q14.E 95,9.95 R29.2 99.5,10.1 99.5,2 77,2 | 77,2 23,2 v23,4 | R25.2 77,13.6 77,2
  Top 0.5: v54,58.5 54,73.5 60,79.5 130.5,79.5 134.5,75.5 134.5,65.5 133.5,64.5 | Q12.E 71.35,13.45 R25.2 | 126.5,2 127,5 127,9 125.9,10.1 R27.2 120.5,11 120,11.5 118.65,11.5 Q13.E | 99.5,2 126.5,2 | 126.5,2 133.5,4.5 133.5,64.5 | 133.5,64.5 122.96,64.5 121.75,65.71 U$1.3 121.54,66 L1.2
  Bottom 0.406: Q24.E 55.15,52.95 R54.2 55,57.5 54.08,58.42 54.08,58.6 51,54
  Bottom 0.5: 6.5,6 6.5,5 8.15,5 TPS1.1 | 6.5,6 6.5,10.5 7.5,11.5 19.5,11.5 21,10 C3.1 21,9 20.73,9.27 C7.2 | 6.5,6 6.27,6.23 | OK2.1 132.5,64.27 132.5,68 124.5,68 v122.5,66 U$1.3 | v54,58.5 51,54 R1.2 | 24,6 23.9,5.9
  Bottom 1: 6.27,6.23 IC1.3
  pour Bottom (isolate 1, rank 3): 24,3.5 24,10 20.5,10 21,7.5 22,3.5
A  (1 unrouted)
  Top 0.5: D10.C 64.11,37.81
  Top 3: X1.A 77.44,37.81 C11.1 64.11,37.81
  Bottom 0.5: C11.1 71.99,37.81
B1C2  (via drill 0.6 pad 1.5)  (2 unrouted)
  Top 0.5: v111,63 110,64 v110,76
  Bottom 0.406: Q20.C 111.1,77.6 111,77.5 111,74.1 R37.1
  Bottom 0.5: v111,63 R38.1 114.45,64.6 Q21.B | v110,76 110.9,75.1 R37.1
BOOST_EN  (via drill 0.5 pad 1.5, 0.6 pad 1.5)
  Top 0.4: 27.5,31.5 33.5,37.5
  Top 0.406: 45.5,54.5 v60.5,54.5
  Top 0.5: 45.5,54.5 33.5,42.5 33.5,37.5 | 27.5,31.5 21.5,31.5 14,24 v14,16
  Bottom 0.406: 60.5,54.1 R6.2 | v60.5,54.5 60.5,54.1 | Q24.C 59.6,52.1 60.5,53 60.5,54.1
  Bottom 0.5: D19.C 14,17 v14,16
C1  (1 unrouted)
  Bottom 0.5: Q21.C 119.6,68.5 U$1.4 121.5,68.75 121.5,70 | 121.5,70 L1.1 | D8.K 125.58,70 121.5,70
CB
  Bottom 0.406: 134,56.5 134,4 33.8,4 D3.C
  Bottom 0.5: D3.C 27.8,7.7 27.5,8 27.5,7.45 QVLIM.1 26.1,5.75 RBZEN1.2
  Bottom 1: 129,59 131.5,59 134,56.5 | 129,59 300U.2 | OK2.2 128.73,59.27 129,59
  pour Bottom (isolate 1, rank 3): 26,10 30.5,10 31,9.5 31,7.5 30.5,7 28,7 26.5,5.5 26,5.5 25.5,6 25.5,9.5
CMPIC3  (1 unrouted)
DCBUS  (via drill 0.6)  (2 unrouted)
  Top 0.5: 32.69,9.31 32,10 31.1,10 C12.2 28.2,7.1 C13.1 | IC2.5 33.05,10.05 v33.5,11 | v11,28.5 11.5,28
  Bottom 0.5: 15.23,30 16.5,28.5 17.65,27 Q22.1 | v33.5,11 33,11 | v11,28.5 R61.1 11.4,30 R49.S
  Bottom 1: R49.S 15.23,30
DCBUS1  (4 unrouted)
EB  (1 unrouted)
  Bottom 0.5: Q21.E 116,68.85 R36.2 118.2,70.9 118.5,71.2 R40.1 119,71.1 119.4,71.2 120.9,72.9 121,73 124,73 124,73.05 RTOP2.2
G  (1 unrouted)
  Top 0.5: 68.5,45.5 68.49,45.8 | R52.2 31.1,27.8 D9.A
  Top 3: D9.A 47.3,45.5 68.5,45.5 | 68.49,45.8 C10.1
  Bottom 0.406: 74.5,53 D5.C | X1.G 83.5,55 84,55.5 98.95,55.5 99.45,56
  Bottom 0.5: 107,70.5 102.5,70.5 99.5,66.5 99.5,59.05 RBZEN.1 99.45,56 RTOP1.2 | 107,70.5 112.5,70.5 112.75,70.25 | 112.75,70.25 113,70 C8.2 | 112.75,70.25 112.75,71.25 113.5,72 114.9,72 R36.1 116,74.85 Q20.E | OK2.4 131,71.27 131,80 130.5,80.5 110.5,80.5 107,77 107,70.5
  Bottom 3: X1.G 81,53 74.5,53 C10.1
GND1
  Bottom 0.5: TPS1.4 10.8,8.15 C6.1
M  (via drill 0.6)
  Top 0.406: v87,52.5 v87,58.5
  Bottom 0.406: X1.M v87,52.5 | v87,58.5 87,60.2 D1.C
N$1
  Bottom 0.5: RBZEN.2 300U.1
N$3
  Bottom 0.5: OK2.3 128.73,74.32 RTOP2.1
N$4  (1 unrouted)
  Bottom 0.406: 35,41 39,39.5
  Bottom 0.5: Q8.1 111.5,32.35 111.5,31 113.5,29 116.5,29 121.5,24 121.5,16.5 | R58.1 35,41
N$5
  Bottom 0.5: 14,71.73 OK1.1 | 14,71.73 17,71.73 C2.+ | R12.S 14.5,66 13.5,67 13.5,71.23 14,71.73
N$6
  Bottom 0.406: 45,48 43.5,48.5
  Bottom 0.5: 43.5,48.5 R43.1 | 45,48 45,34 46,33 56,33 56,33.85 Q3.1
N$7
  Bottom 0.5: Q6.3 119.5,38.75 LED6.C
N$8
  Bottom 0.5: R17.2 16.1,8 R18.2
N$10
  Bottom 0.5: Q8.3 110.5,37.75 LED8.C
N$11
  Bottom 0.5: Q2.1 60.95,31.45 60.5,31 45,31 43,33 43,46 R42.1
N$12
  Bottom 0.406: 41,29 41,42
  Bottom 0.5: Q1.1 64.45,29.95 63.5,29 41,29 | 41,42 39.5,43.5 R41.1
N$13
  Top 0.5: TR1.5 34.25,25.75 | 38.5,30 40.7,30 D9.C
  Top 3: 34.25,25.75 38.5,30 | D9.C D10.A
N$14
  Bottom 0.406: R55.1 4,26 4,13.5 | 126.5,13.5 126.5,31.35 Q5.1
  Bottom 0.5: 4,13.5 126.5,13.5
N$15  (via drill 0.6)
  Top 0.5: v39.48,21.25 Q19.3
  Top 3: Q18.3 30.98,21.77 TR1.1 v39.48,21.25
N$16
  Bottom 0.406: 5M.1 132,55.5 132,6 35.5,5 31,10.5 27,10.5 QVLIM.3
N$17
  Bottom 0.5: LED7.C 116,35.6 Q7.3
N$18
  Bottom 0.5: R16.1 22.5,74 62.5,74 D15.A
N$19
  Bottom 0.5: LED1.C 62.75,37.75 63.5,35 Q1.3
N$20
  Bottom 0.5: LED1.A 61.65,43.75 R3.1
N$21  (via drill 0.6)
  Top 0.5: v98,8.5 98,7.9 R29.1 95,7 94.5,6.5 92.5,6.5 92.1,6.9 Q14.B
  Bottom 0.5: R11.2 116,51.5 116.5,51.5 116.5,52 129,52 129,9.5 128.5,9 99,9 98.5,8.5 v98,8.5
N$22
  Bottom 0.5: LED2.C 59,38.1 Q2.3
N$23
  Bottom 0.5: D15.C D14.A
N$24
  Bottom 0.5: D14.C D13.A
N$25
  Bottom 0.5: LED2.A R28.1
N$26
  Bottom 0.5: R12.A 12.44,63.46 R13.2
N$27  (via drill 0.6)  (3 unrouted)
  Top 0.5: 36.79,6.69 IC2.3 | 36.79,6.69 R59.1 | C16.2 37.45,6.04 36.79,6.69 | v16.5,18 16.5,17.5 | R69.1 37.66,6.84 v37.5,7
  Bottom 0.5: R46.1 10.9,22.4 12,22.5 D19.A 14,21.5 16,19.5 16.8,19.5 D18.C v16.5,18 | v37.5,7 38,7.5
N$28  (1 unrouted)
  Bottom 0.406: 125,14.5 125,27 120.5,31.5 120.5,32.35 Q6.1
  Bottom 0.5: R56.1 37,34.9
N$29
  Bottom 0.5: RTOP1.1 5M.2
N$30
  Bottom 0.406: R44.1 36,50.5 47,50.5 47,36 47.5,35.5 48.45,35.5 Q4.1
N$31  (1 unrouted)
  Bottom 0.5: Q7.1 116,31.85 118.5,29.5 120,29.5 123,26.5 123,15.5 | 38,37 35,38.5 R57.1
N$32
  Bottom 0.406: Q3.3 LED3.C
N$33
  Bottom 0.5: LED4.C 51,36.6 Q4.3
N$34
  Bottom 0.5: R19.1 52.6,64.2 D7.A
N$35
  Bottom 0.5: D7.C 56.8,64 D6.A
N$36
  Bottom 0.5: LED4.A R1.1
N$37
  Top 0.5: Q12.C 65.9,10 R30.2
N$38
  Bottom 0.5: D6.C 63.7,60.1 D5.A
N$39
  Bottom 0.5: R10.E 50.36,68.54 R19.2
N$40
  Bottom 0.5: R10.A 46.77,59.33 R20.2
N$41
  Bottom 0.406: D4.A 68.5,60.5 63,66 60.5,66 54.5,72 37.5,72 35.5,70.5 33.5,70.6 R4.1
N$42
  Bottom 0.5: D4.C D2.A
N$43
  Bottom 0.5: D2.C D1.A
N$44
  Bottom 0.5: R2.E 28.77,68.27 29,68.5 R4.2
N$45
  Bottom 0.5: R2.A 28.77,59.37 R5.2
N$46
  Bottom 0.5: R8.1 R2.S 31.77,65.5 C4.+
N$47
  Bottom 0.5: LED5.A R9.1
N$48
  Bottom 0.5: R22.1 41.4,67.1 42,66.5 C5.+ 43.23,66 R10.S
N$49
  Top 0.5: Q14.C 89.9,8.9 89,8 89,7 88,6 81,6 80,7 R35.2
N$50
  Top 0.5: Q15.B 54.54,18.54 52,16 52,8.4 53,7.4 R31.2 59,7.4 | 59,7.4 R30.1 | R23.2 58.9,7.5 59,7.4
N$51
  Top 0.5: Q16.B 104.54,13.96 106,12.5 | 106,12.5 107.69,12.5 Q10.1 108.9,11.29 R24.2 | R34.1 105,11.5 106,12.5
N$52
  Bottom 0.5: Q5.3 LED5.C
N$53  (via drill 0.6)
  Top 0.5: v75,11 71.9,11 R25.1 71.35,11.55 Q12.B
  Bottom 0.406: R7.2 119.5,48.1 119.5,50.5 128,50.5 128,11 76,11
  Bottom 0.5: v75,11 76,11
N$54
  Top 0.5: R31.1 56,12 57.25,12 Q9.1
N$55  (via drill 0.6)
  Top 0.5: v124.5,7.5 123.5,7 122.6,7.9 R27.1 119.6,7 118,7 117.6,7.4 Q13.B
  Bottom 0.5: R21.2 109.9,49.9 113.5,53.5 129.5,53.5 130,53 130,7.5 v124.5,7.5
N$56  (via drill 0.5 pad 1.5)
  Top 0.406: v18.5,16 18.5,15 18,14.5 17.5,14.69 Q18.1
  Bottom 0.406: R33.1 19.6,15.9 v18.5,16
N$57
  Top 0.5: R34.2 105,7.5 105.5,7 115,7 115.5,7.5 115.5,9.4 Q13.C
N$58
  Top 0.5: R32.1 37.79,13.9 Q19.1
N$59
  Top 0.406: Q17.B 79.54,14.46 81.5,12.5 82.69,12.5 Q11.1 82.72,10.18 R26.2
  Top 0.5: R35.1 80,11 81.5,12.5
N$60
  Bottom 0.5: R37.2 113.1,75.85 U$1.1
N$61
  Bottom 0.5: C8.1 113,66.25 U$1.2
N$62
  Bottom 0.5: R38.2 R39.2
N$63
  Bottom 0.5: R40.2 118.45,73.65 Q20.B
N$64  (1 unrouted)
  Bottom 0.5: 9.75,25.25 TR1.7 | 9,25 8.5,24.9 R46.2
  Bottom 1: 9,25 9.75,25.25
N$65
  Bottom 0.5: R12.E 19.04,68.54 20.5,70 20.5,70.9 R16.2
N$66  (via drill 0.6 pad 1.5)  (1 unrouted)
  Top 0.5: R32.2 33.5,16 32,16 | 32,16 v31.25,16 | R59.2 35.24,9.6 IC2.4 35,9.36 35,12 R60.1 33.1,14.9 32,16
  Bottom 0.406: R33.2 R51.1
  Bottom 0.5: R51.1 25.2,19.4 Q23.3 | R45.1 26.05,21 30,21 31,20 31,17 v31.25,16
N$67
  Top 0.5: C13.2 28,11 29,13 R60.2
N$68  (via drill 0.6)
  Top 0.5: Q19.2 v43.97,12.47 45.5,14 45.7,14 R47.2
N$69  (1 unrouted)
N$71
  Bottom 0.5: Q22.3 19.5,22.1 R51.2
N$72  (via drill 0.6 pad 1.5)
  Top 0.5: 25.63,14.47 R48.2 26.8,16 v28,16
  Top 2: Q18.2 25.63,14.47
  Bottom 0.5: Q23.1 28.1,16.4 v28,16
N$73
  Bottom 0.5: 16.76,32.54 D16.A
  Bottom 1: R49.A 16.76,32.54
N$74
  Bottom 0.5: C9.1 9.35,16.6 TR1.9
N$75  (2 unrouted)
N$76
  Bottom 0.5: D16.C 20.2,29.9 D12.A
N$77
  Bottom 0.5: D17.A 23.8,30 23,29.5 D12.C
N$78
  Bottom 1: R50.1 13.4,27.38 R49.E
N$79  (via drill 0.6 pad 1.5)  (1 unrouted)
  Top 0.5: 52,37.5 D11.A
  Bottom 0.5: v30.5,31 29.9,32 D17.C
N$80  (via drill 0.6 pad 1.5)  (1 unrouted)
  Top 0.5: R52.1 26,27.5 v26,25.75
  Bottom 0.5: R45.2 v26,25.75
N$81
  Bottom 0.406: R53.2 R54.1 57.25,50.9 Q24.B 57.45,51
N$82
  Bottom 0.406: LED3.A R53.1
N$83  (1 unrouted)
N$84  (1 unrouted)
N$85  (3 unrouted)
N$86  (2 unrouted)
N$87  (1 unrouted)
N$88  (3 unrouted)
N$90  (1 unrouted)
N$91  (1 unrouted)
N$92  (1 unrouted)
N$93  (3 unrouted)
N$94  (1 unrouted)
N$95  (2 unrouted)
N$96
  Top 0.5: C17.2 31.55,5.19 IC2.1
N$97  (1 unrouted)
RB0  (via drill 0.6 pad 1.5)
  Top 0.406: v34.5,58 32.5,55.5 6,55.5 6,44 6.5,43 JP3.4
  Bottom 0.406: R22.2 36,58 v34.5,58
  Bottom 0.5: JP3.4 9.54,42.96 10.54,42.96 13,40.5 14.5,40.5 14.96,40.96 MIC.13
RB1  (via drill 0.6 pad 1.5)
  Top 0.406: v22.5,58 4,58 4,40.5 9.46,40.5 JP3.5
  Bottom 0.406: R8.2 22.5,65.5 v22.5,58
  Bottom 0.5: JP3.5 9.54,40.5 10,40.5 9.97,40.47 9.97,40.42 12.5,39 16,39 16.2,39.31 16.23,39.34 MIC.12
RB2  (via drill 0.6 pad 1.5)
  Top 0.406: v5,60.5 2,60.5 2,39 2.5,38 9.42,38 JP3.6
  Bottom 0.406: R14.2 4.5,61 v5,60.5
  Bottom 0.5: MIC.11 17.5,37.3 10.88,37.3 | 10.88,37.3 9.19,37.8 | JP3.6 10.88,37.3 | OK1.4 5.19,67.21 R14.2
RB4
  Bottom 0.5: MIC.3 16.23,46.27 17,45.5 24,45.5 25.5,43 JP6.4 28.5,43 29,43.5
RB5
  Bottom 0.5: MIC.2 14.96,45.54 16,44.5 23,44.5 23,40.5 JP6.3 27.54,41 R58.2
RC0
  Bottom 0.5: MIC.10 18.77,35.5 11.5,35.5 8.73,35.3 9.42,35.3 JP3.7 | R55.2 JP3.7 | R61.2 11,33.88 JP3.7
RC1
  Bottom 0.5: MIC.9 20.04,36.46 21,35.3 26.88,35.3 JP6.1 27.5,35.38 | 27.5,35.38 27.83,35.38 28.45,36 R56.2 | 27.5,35.38 27.62,35.5
RC2
  Bottom 0.5: MIC.8 21.31,38.99 22.1,38 25.08,38 JP6.2 27.58,38.5 R57.2
RC3
  Bottom 0.5: MIC.7 24.14,47.36 25.5,46 26,46 26.5,45.5 26.96,45.5 JP6.5 27.46,46 R42.2
RC4
  Bottom 0.5: MIC.6 20,47.4 20,49.5 24,49.5 25.42,48.08 JP6.6 27.42,48.5 R43.2
RC5
  Bottom 0.5: MIC.5 18.77,48.96 18.8,48.99 18.8,50.4 19.12,50.62 JP6.7 27.38,51 R44.2
S  (via drill 0.6)
  Top 0.5: v93.5,71.5 v93.5,54
  Bottom 0.5: X1.S 93.5,49.5 v93.5,54 | 15,77 14.5,75 13.5,74 13.08,74 OK1.2 12.58,74.5 12,74.5 11,73.5 R13.1 | 15,77 90,77 93.5,72 v93.5,71.5 | C2.- 15.73,74.77 15,77
T  (via drill 0.6)
  Top 0.5: v90.5,52.5 v90.5,65.5
  Bottom 0.5: D13.C 90,66 v90.5,65.5 | X1.T v90.5,52.5
U
  Top 0.5: 95.38,40.12 X1.U | Q17.C 85,24.96
  Top 3: 95.38,40.12 97,38.5 97,35.5 91.5,30 86.5,30 85,28 85,24.96 | Q11.3 Q17.C
V+  (2 unrouted)
  Bottom 0.5: TPS1.5 12.45,5.1 R15.2 13.5,4.5 13,3.5 4.5,3.5 3.73,4.27 | MIC.1 12.97,48.08 JP3.2 5.68,48.08 C1.1 2.5,47.9 2,48 | 2,48 2,63.5 2,65.5 R14.1 | 2,8.23 2,48
  Bottom 1: 3.73,4.27 IC1.1 2,8.23
V-  (6 unrouted)
  Bottom 0.5: TPS1.2 TPS1.3 8.5,8.15 8.5,8.5 8.55,8.55 C6.2 8.55,10.55 9,10.5 12.9,10.5 R17.1 13.9,9.9 13.5,9.5 R15.1
VCCIC3  (4 unrouted)
VSS  (via drill 0.8)  (44 unrouted)
  Top 0.5: OK1.3 6.23,74.27 8,72.5 8,62.5 11,59.5 | IC2.2 34,4.5 C17.1
  Bottom 0.5: MIC.14 13.69,42.81 11,45.5 | JP3.3 9.54,45.5
  Bottom 1.5: 9.54,45.5 11,45.5
  other vias: 68,41.5 73.5,32
  pour Bottom (isolate 2, rank 4): 1,59 17.5,63 48.5,63 60,54.5 79.5,54.5 82,49 101.5,49 104,55 106,55 106,78 134,78 134,2 0.5,2 0.5,54.5
  pour Top (isolate 2, rank 4, no thermals): 1.5,60 79,60 82,49 101.5,49 104,51.5 106,51.5 108,54 133,54.5 132.5,2 0.5,2 0.5,54.5
WIND
  Bottom 0.5: MIC.4 17.5,50 17.42,50.58 9,50.58 | 9,50.58 8.57,50.58 | 9.5,50.5 JP3.1 9.04,50.62 9,50.58
Y
  Top 0.5: 110,24.96 Q16.C Q10.3
  Top 3: X1.Y 99.62,45.88 110,35 110,24.96

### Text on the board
Top: MICHAEL5.net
